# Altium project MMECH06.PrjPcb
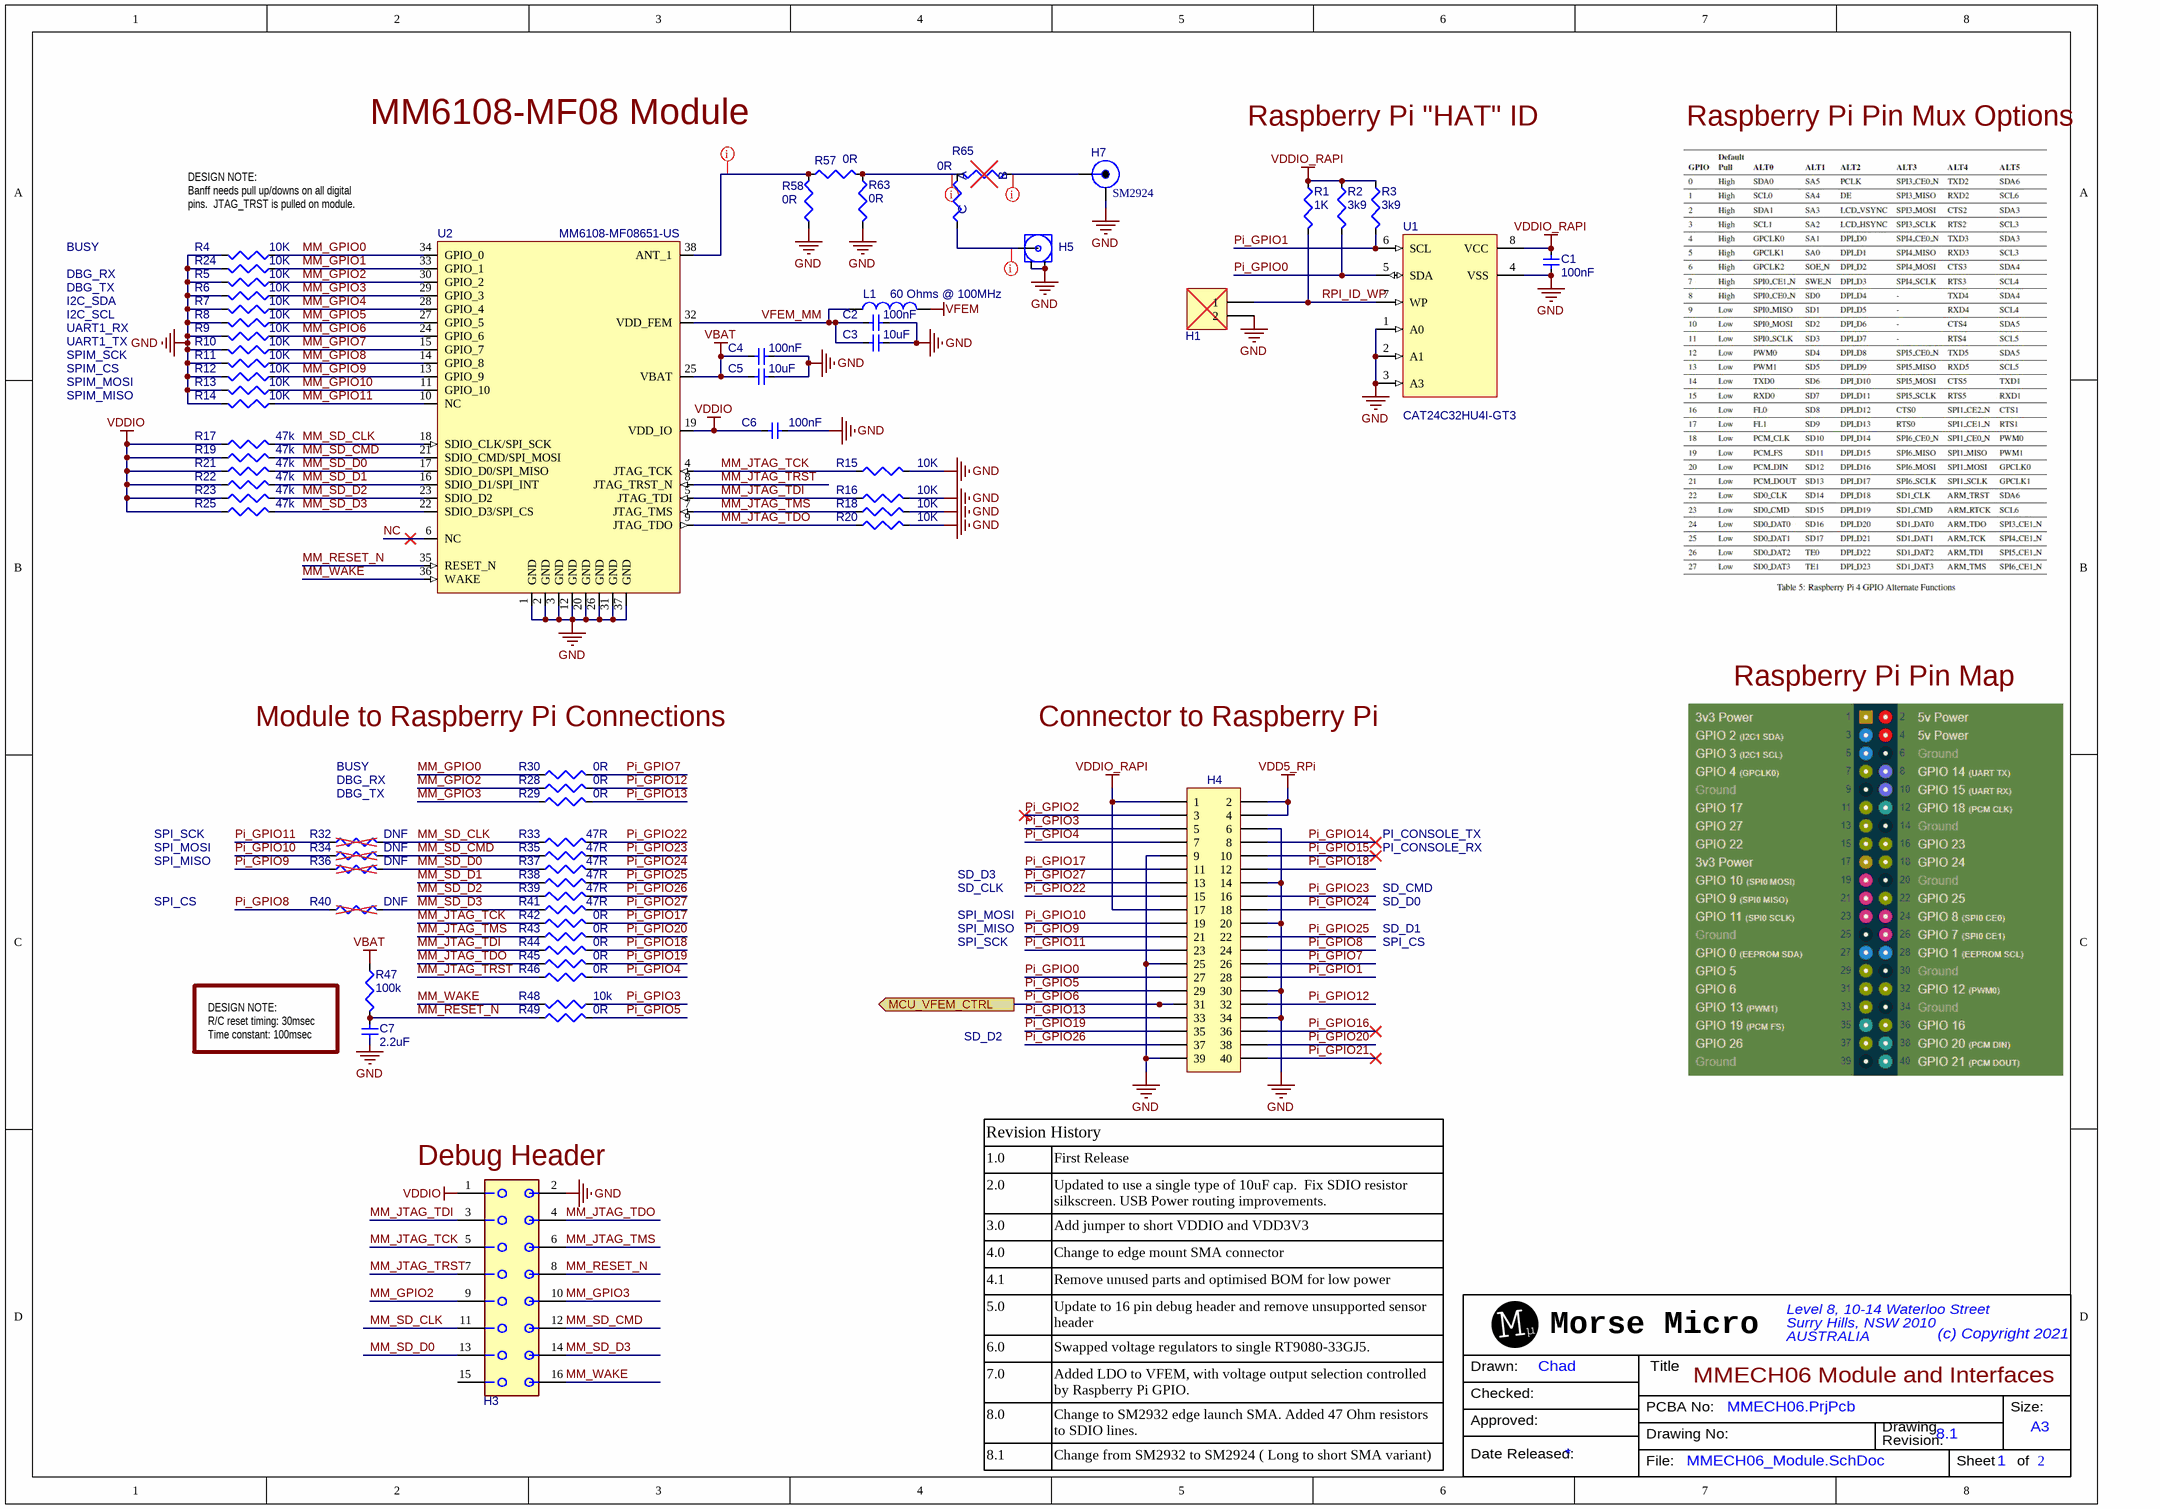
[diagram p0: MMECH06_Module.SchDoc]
Project: MM_EVC3; Revision: 1
2 sheets, 107 parts. Net scope: flat (ports and power ports of the same name join across sheets).
Board file: MMECH06.PcbDoc
Sheets:
  MMECH06_Module.SchDoc
  MMECH06_Power.SchDoc

## Sheet MMECH06_Module.SchDoc: MMECH06 Module and Interfaces
size A3; DrawnBy: Chad; Revision: 8.1; SheetNumber: 1; SheetTotal: 2; PageSetup: Record=PageOptions¦CenterHorizontal=True¦CenterVertical=True¦PrintScale=1.04¦XCorrection=1.00¦YCorrection=1.00¦PrintKind=0¦BorderSize=5000000¦LeftOffset=0¦BottomOffset=0¦Orientation=2¦PaperLength=1000¦PaperWidth=1000¦Scale=100¦PaperSource=7¦PrintQuality=-4¦MediaType=1¦DitherType=10¦PaperKind=A3¦PrintScaleMode=1

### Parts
C1  value 100nF  [CAPC1005X06N]  (hidden comment: CAP)
C2  value 100nF  [CAPC1005X06N]  (hidden comment: CAP)
C3  value 10uF  [CAPC1608X06N]  (hidden comment: CAP)
C4  value 100nF  [CAPC1005X06N]  (hidden comment: CAP)
C5  value 10uF  [CAPC1608X06N]  (hidden comment: CAP)
C6  value 100nF  [CAPC1005X06N]  (hidden comment: CAP)
C7  value 2.2uF  [CAPC1005X06N]  (hidden comment: CAP)
H1  HDR_1X2_DNF  [HDR1X2_DNF]  (value not drawn)  (no BOM)
H3  2X8_FTSH_DV_K  [FTSH_108_D_K]  (value not drawn)
H4  HDR_2X20  [HDR2X20F]  (value not drawn)
H5  U_FL-R-SMT  [U_FL-R-SMT]  (value not drawn)
H7  SM2924  [SM2924-Footprint-1]
L1  value 60 Ohms @ 100MHz  [INDC1005X06N]  (hidden comment: IND)
R1  value 1K  [RESC1005X04N]  (hidden comment: RES)
R2  value 3k9  [RESC1005X04N]  (hidden comment: RES)
R3  value 3k9  [RESC1005X04N]  (hidden comment: RES)
R4  value 10K  [RESC1005X04N]  (hidden comment: RES)
R5  value 10K  [RESC1005X04N]  (hidden comment: RES)
R6  value 10K  [RESC1005X04N]  (hidden comment: RES)
R7  value 10K  [RESC1005X04N]  (hidden comment: RES)
R8  value 10K  [RESC1005X04N]  (hidden comment: RES)
R9  value 10K  [RESC1005X04N]  (hidden comment: RES)
R10  value 10K  [RESC1005X04N]  (hidden comment: RES)
R11  value 10K  [RESC1005X04N]  (hidden comment: RES)
R12  value 10K  [RESC1005X04N]  (hidden comment: RES)
R13  value 10K  [RESC1005X04N]  (hidden comment: RES)
R14  value 10K  [RESC1005X04N]  (hidden comment: RES)
R15  value 10K  [RESC1005X04N]  (hidden comment: RES)
R16  value 10K  [RESC1005X04N]  (hidden comment: RES)
R17  value 47k  [RESC1005X04N]  (hidden comment: RES)
R18  value 10K  [RESC1005X04N]  (hidden comment: RES)
R19  value 47k  [RESC1005X04N]  (hidden comment: RES)
R20  value 10K  [RESC1005X04N]  (hidden comment: RES)
R21  value 47k  [RESC1005X04N]  (hidden comment: RES)
R22  value 47k  [RESC1005X04N]  (hidden comment: RES)
R23  value 47k  [RESC1005X04N]  (hidden comment: RES)
R24  value 10K  [RESC1005X04N]  (hidden comment: RES)
R25  value 47k  [RESC1005X04N]  (hidden comment: RES)
R28  value 0R  [RESC1608X06N]  (hidden comment: RES)
R29  value 0R  [RESC1608X06N]  (hidden comment: RES)
R30  value 0R  [RESC1608X06N]  (hidden comment: RES)
R32  value DNF  [RESC1608X06N_DNF]  (hidden comment: RES_DNF)  (no BOM)
R33  value 47R  [RESC1608X06N]  (hidden comment: RES)
R34  value DNF  [RESC1608X06N_DNF]  (hidden comment: RES_DNF)  (no BOM)
R35  value 47R  [RESC1608X06N]  (hidden comment: RES)
R36  value DNF  [RESC1608X06N_DNF]  (hidden comment: RES_DNF)  (no BOM)
R37  value 47R  [RESC1608X06N]  (hidden comment: RES)
R38  value 47R  [RESC1608X06N]  (hidden comment: RES)
R39  value 47R  [RESC1608X06N]  (hidden comment: RES)
R40  value DNF  [RESC1608X06N_DNF]  (hidden comment: RES_DNF)  (no BOM)
R41  value 47R  [RESC1608X06N]  (hidden comment: RES)
R42  value 0R  [RESC1608X06N]  (hidden comment: RES)
R43  value 0R  [RESC1608X06N]  (hidden comment: RES)
R44  value 0R  [RESC1608X06N]  (hidden comment: RES)
R45  value 0R  [RESC1608X06N]  (hidden comment: RES)
R46  value 0R  [RESC1608X06N]  (hidden comment: RES)
R47  value 100k  [0402_res_rnd]  (hidden comment: RES)
R48  value 10k  [RESC1608X06N]  (hidden comment: RES)
R49  value 0R  [RESC1608X06N]  (hidden comment: RES)
R57  value 0R  [RESC1608X06L]  (hidden comment: RES)
R58  value 0R  [RESC1608X06L]  (hidden comment: RES)
R63  value 0R  [RESC1608X06L]  (hidden comment: RES)
R65  value 0R  [0603_RES_AC_RA]  (hidden comment: RES_AC)
U1  CAT24C32HU4I-GT3  [DFN8]
U2  MM6108-MF08651-US  [MF04]

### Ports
MCU_VFEM_CTRL (out)

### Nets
GND: C1.2 C2.2 C3.2 C4.1 C5.2 C6.2 C7.2 H1.2 H3.2 H4.6 H4.9 H4.14 H4.20 H4.25 H4.30 H4.34 H4.39 H5.2 H5.3 H7.2 R4.2 R5.2 R6.2 R7.2 R8.2 R9.2 R10.2 R11.2 R12.2 R13.2 R14.2 R15.2 R16.2 R18.2 R20.2 R24.2 R58.1 R63.2 U1.1(A0) U1.2(A1) U1.3(A3) U1.4(VSS) U2.1(GND) U2.2(GND) U2.3(GND) U2.12(GND) U2.20(GND) U2.26(GND) U2.31(GND) U2.37(GND)
VBAT: C4.2 C5.1 R47.1 U2.25(VBAT)
VDD5_RPi: H4.2 H4.4
VDDIO: C6.1 H3.1 R17.1 R19.1 R21.2 R22.2 R23.2 R25.1 U2.19(VDD_IO)
VDDIO_RAPI: C1.1 H4.1 H4.17 R1.1 R2.1 R3.1 U1.8(VCC)
VFEM: L1.2
MM_GPIO0: R4.1 R30.1 U2.34(GPIO_0)
MM_GPIO1: R24.1 U2.33(GPIO_1)
MM_GPIO2: H3.9 R5.1 R28.1 U2.30(GPIO_2)
MM_GPIO3: H3.10 R6.1 R29.1 U2.29(GPIO_3)
MM_GPIO4: R7.1 U2.28(GPIO_4)
MM_GPIO5: R8.1 U2.27(GPIO_5)
MM_GPIO6: R9.1 U2.24(GPIO_6)
MM_GPIO7: R10.1 U2.15(GPIO_7)
MM_GPIO8: R11.1 U2.14(GPIO_8)
MM_GPIO9: R12.1 U2.13(GPIO_9)
MM_GPIO10: R13.1 U2.11(GPIO_10)
MM_GPIO11: R14.1 U2.10(NC)
MM_JTAG_TCK: H3.5 R15.1 R42.1 U2.4(JTAG_TCK)
MM_JTAG_TDI: H3.3 R16.1 R44.1 U2.5(JTAG_TDI)
MM_JTAG_TDO: H3.4 R20.1 R45.1 U2.9(JTAG_TDO)
MM_JTAG_TMS: H3.6 R18.1 R43.1 U2.7(JTAG_TMS)
MM_JTAG_TRST: H3.7 R46.1 U2.8(JTAG_TRST_N)
MM_RESET_N: C7.1 H3.8 R47.2 R49.1 U2.35(RESET_N)
MM_SD_CLK: H3.11 R17.2 R32.2 R33.1 U2.18(SDIO_CLK/SPI_SCK)
MM_SD_CMD: H3.12 R19.2 R34.2 R35.1 U2.21(SDIO_CMD/SPI_MOSI)
MM_SD_D0: H3.13 R21.1 R36.2 R37.1 U2.17(SDIO_D0/SPI_MISO)
MM_SD_D1: R22.1 R38.1 U2.16(SDIO_D1/SPI_INT)
MM_SD_D2: R23.1 R39.1 U2.23(SDIO_D2)
MM_SD_D3: H3.14 R25.2 R40.2 R41.1 U2.22(SDIO_D3/SPI_CS)
MM_WAKE: H3.16 R48.1 U2.36(WAKE)
NC: U2.6(NC)
Pi_GPIO0: H4.27 R2.2 U1.5(SDA)
Pi_GPIO1: H4.28 R3.2 U1.6(SCL)
Pi_GPIO2: H4.3
Pi_GPIO3: H4.5 R48.2
Pi_GPIO4: H4.7 R46.2
Pi_GPIO5: H4.29 R49.2
Pi_GPIO6: H4.31 ; port MCU_VFEM_CTRL
Pi_GPIO7: H4.26 R30.2
Pi_GPIO8: H4.24 R40.1
Pi_GPIO9: H4.21 R36.1
Pi_GPIO10: H4.19 R34.1
Pi_GPIO11: H4.23 R32.1
Pi_GPIO12: H4.32 R28.2
Pi_GPIO13: H4.33 R29.2
Pi_GPIO14: H4.8
Pi_GPIO15: H4.10
Pi_GPIO16: H4.36
Pi_GPIO17: H4.11 R42.2
Pi_GPIO18: H4.12 R44.2
Pi_GPIO19: H4.35 R45.2
Pi_GPIO20: H4.38 R43.2
Pi_GPIO21: H4.40
Pi_GPIO22: H4.15 R33.2
Pi_GPIO23: H4.16 R35.2
Pi_GPIO24: H4.18 R37.2
Pi_GPIO25: H4.22 R38.2
Pi_GPIO26: H4.37 R39.2
Pi_GPIO27: H4.13 R41.2
RPI_ID_WP: H1.1 R1.2 U1.7(WP)
VFEM_MM: C2.1 C3.1 L1.1 U2.32(VDD_FEM)
NetH5_1: H5.1 R65.C
NetH7_1: H7.1 R65.B
NetR57_1: R57.1 R58.2 U2.38(ANT_1)
NetR57_2: R57.2 R63.1 R65.A

Not connected (* = marked no-connect by the designer): H3 15

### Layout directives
net class RF-Net: NetH5_1, NetH7_1, NetR57_1, NetR57_2

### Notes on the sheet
- #800000
- MM6108-MF08 Module
- Raspberry Pi "HAT" ID
- Raspberry Pi Pin Mux Options
- DESIGN NOTE:
  Banff needs pull up/downs on all digital pins.  JTAG_TRST is pulled on module.
- DBG_RX
- DBG_TX
- BUSY
- I2C_SDA
- I2C_SCL
- SPIM_SCK
- SPIM_CS
- UART1_RX
- UART1_TX
- SPIM_MOSI
- SPIM_MISO
- Raspberry Pi Pin Map
- Module to Raspberry Pi Connections
- Connector to Raspberry Pi
- SPI_MOSI
- SPI_SCK
- PI_CONSOLE_TX
- PI_CONSOLE_RX
- SPI_MISO
- SPI_CS
- SD_CLK
- SD_D3
- SD_CMD
- SD_D0
- SD_D1
- DESIGN NOTE:
  R/C reset timing: 30msec
  Time constant: 100msec
- SD_D2
- (near H3) Debug Header
- Revision History
- 1.0
- First Release
- 2.0
- 3.0
- 4.0
- Updated to use a single type of 10uF cap.  Fix SDIO resistor silkscreen. USB Power routing improvements.
- Add jumper to short VDDIO and VDD3V3
- Change to edge mount SMA connector
- 4.1
- Remove unused parts and optimised BOM for low power
- 5.0
- 6.0
- 7.0
- Update to 16 pin debug header and remove unsupported sensor header
- Swapped voltage regulators to single RT9080-33GJ5.
- Added LDO to VFEM, with voltage output selection controlled by Raspberry Pi GPIO.
- 8.0
- Change to SM2932 edge launch SMA. Added 47 Ohm resistors to SDIO lines.
- 8.1
- Change from SM2932 to SM2924 ( Long to short SMA variant)

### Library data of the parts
C1 C2 C4 C6 = CAP0084: Cap,100nF,10V,+/-10%,X7R,0402; Manufacturer 1: Kemet; Manufacturer Part Number 1: C0402C104K8RACTU; Generic Allowed: Yes; Subtype: Ceramic; Tolerance: 10%
C3 C5 = CAP0164: CAP CER 10UF 25V 20% X5R 0603; Manufacturer 1: Murata, Inc.; Manufacturer Part Number 1: GRM188R61E106MA73J; Generic Allowed: Yes; Subtype: Ceramic
C7 = CAP0086: CAP CER 2.2UF 6.3V 20% X5R 0402; Manufacturer 1: Taiyo Yuden; Manufacturer Part Number 1: JMK105BJ225MV-F; Generic Allowed: Yes; Subtype: Ceramic
H1 = HDR0098: Conn Straight Header 2x1 0.100" 2 POS (DNF)
H3 = HDR0143: CONN,Vertical FTSH Series,0.05"16 Pins, Through Hole; Manufacturer 1: Samtec; Manufacturer Part Number 1: FTSH-108-01-F-D-K; Generic Allowed: No
H4 = HDR0151: Conn Female Header 20x2 0.100" 40 POS; Manufacturer 1: Sullins Electronics, Corp; Manufacturer Part Number 1: PPPC202LFBN-RC; Generic Allowed: Yes
H5 = CON0012: U.FL RF Connector; Manufacturer 1: Hirose; Manufacturer Part Number 1: U.FL-R-SMT; Generic Allowed: Yes
H7 = JCK0138-4: Wanshih RF SMD SMA connector with 2 GND pillars - Smaller Connector Barrel
L1 = IND0083: BEAD 60OHMS 2500MA 32 MOHM; Manufacturer 1: Murata; Manufacturer Part Number 1: BLM15PX600SN1D; Current: 2.5A; Generic Allowed: Yes; Resistance: 32mOhm
R1 = RES0004: RES SMD 1Kohm 1% 1/10W Thick film 0402; Manufacturer 1: Panasonic; Manufacturer Part Number 1: ERJ-2RKF1001X; Generic Allowed: Yes
R2 R3 = RES0204: RES SMD 3.9K OHM 1% 1/16W 0402; Manufacturer 1: Yageo; Manufacturer Part Number 1: RC0402FR-073K9L; Generic Allowed: Yes
R4-R16 R18 R20 R24 = RES0002: RES SMD 10Kohm 1% 1/10W Thick film 0402; Manufacturer 1: Panasonic; Manufacturer Part Number 1: ERJ-2RKF1002X; Generic Allowed: Yes
R17 R19 R21-R23 R25 = RES0086: Res, 47K Ohms,1/16W, 1%, 0402,SMD RoHS; Manufacturer 1: Rohm; Manufacturer Part Number 1: MCR01MZPF4702; Generic Allowed: Yes
R28-R30 R42-R46 R49 R57 R58 R63 = RES0119: Res, 0 Ohm, 1/10W,+/-5%,0603 RoHS; Manufacturer 1: Rohm; Manufacturer Part Number 1: MCR03EZPJ000; Generic Allowed: Yes; Tolerance: 5%
R32 R34 R36 R40 = RES0035: Update Later
R33 R35 R37-R39 R41 = RES0282: RES SMD 47 OHM 5% 1/10W 0603; Manufacturer 1: Panasonic Electronic Components; Manufacturer Part Number 1: ERJ-3GEYJ470V; Generic Allowed: Yes; Subtype: Thick Film
R47 = RES0044: Res,100K Ohms,1/16W, 1%, 0402,SMD RoHS; Manufacturer 1: Rohm; Manufacturer Part Number 1: MCR01MZPF1003; Generic Allowed: Yes
R48 = RES0124: Res, 10K Ohm, 1/10W,+/-1%,0603 RoHS; Manufacturer 1: Rohm; Manufacturer Part Number 1: MCR03EZPFX1002; Generic Allowed: Yes; Tolerance: 1%
R65 = RES0281: Ohms Jumper Chip Resistor 0603 ( 1608 Metric) - RES_AB; Manufacturer 1: Rohm; Manufacturer Part Number 1: MCR03EZPJ000; Generic Allowed: Yes; Power: 1/10W; Tolerance: 5%
U1 = ICT0220: IC EEPROM 32KBIT I2C 1MHZ 8UDFN; Manufacturer 1: OnSemi; Generic Allowed: No
U2 = MOD0018: MM61xx-MF08; Manufacturer Part Number 1: MM61xx-MF08251; Manufacturer 1: Morse Micro; Value: MM61xx-MF08251

## Sheet MMECH06_Power.SchDoc: MMECH06 Power & Reset
size A3; CompanyName: Morse Micro; DrawnBy: Chad; Revision: 8.1; SheetNumber: 2; SheetTotal: 2; pageName: Regulators; PageSetup: Record=PageOptions¦CenterHorizontal=True¦CenterVertical=True¦PrintScale=1.04¦XCorrection=1.00¦YCorrection=1.00¦PrintKind=0¦BorderSize=5000000¦LeftOffset=0¦BottomOffset=0¦Orientation=2¦PaperLength=1000¦PaperWidth=1000¦Scale=100¦PaperSource=7¦PrintQuality=-4¦MediaType=1¦DitherType=10¦PaperKind=A3¦PrintScaleMode=1
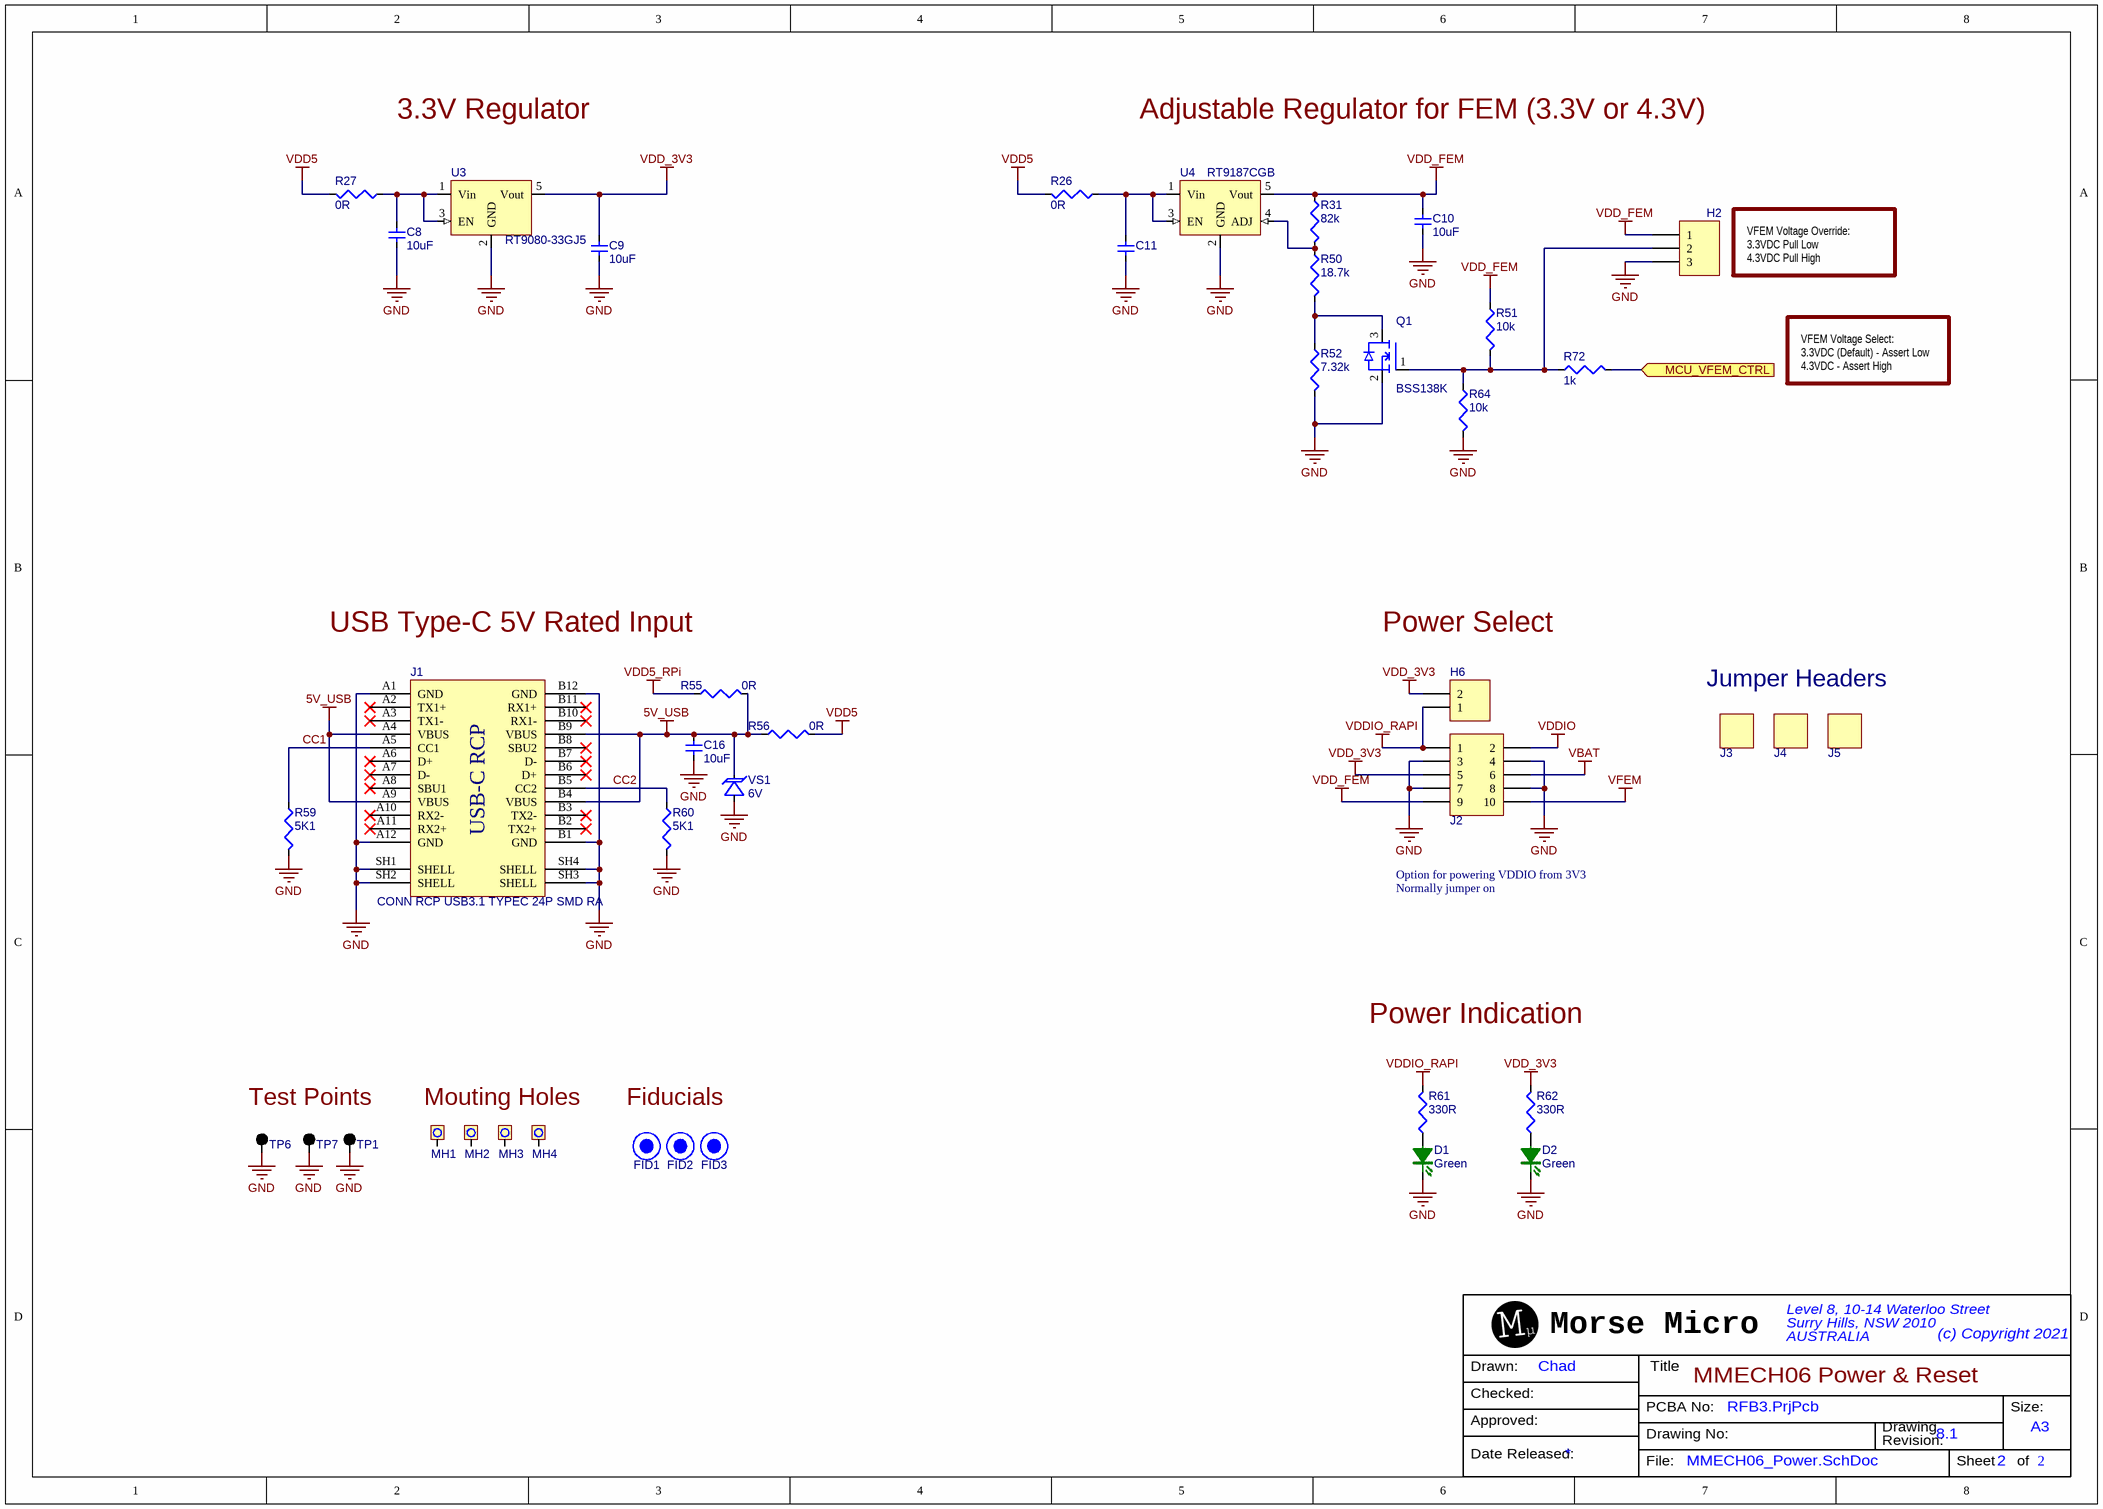
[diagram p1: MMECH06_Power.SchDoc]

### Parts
C8  value 10uF  [CAPC1608X06N]  (hidden comment: CAP)
C9  value 10uF  [CAPC1608X06N]  (hidden comment: CAP)
C10  value 10uF  [CAPC1608X06N]  (hidden comment: CAP)
C11  CAP  [CAPC1608X06N]  (value not drawn)
C16  value 10uF  [CAPC1608X06N]  (hidden comment: CAP)
D1  value Green  [LED_0402_GREEN]  (hidden comment: LED_G)
D2  value Green  [LED_0402_GREEN]  (hidden comment: LED_G)
FID1  FIDUCIAL  [FIDUCIAL_1MM]  (value not drawn)  (no BOM)
FID2  FIDUCIAL  [FIDUCIAL_1MM]  (value not drawn)  (no BOM)
FID3  FIDUCIAL  [FIDUCIAL_1MM]  (value not drawn)  (no BOM)
H2  HDR_1X3  [HPH1A03UA]  (value not drawn)
H6  HDR_1X2  [HDR1X2]  (value not drawn)
J1  CONN RCP USB3.1 TYPEC 24P SMD RA  [USB-C_RCP]
J2  HDR_2X5  [HDR2X5]  (value not drawn)
J3  QPC02SXGN-RC  [QPC02SXGN-RC]  (value not drawn)
J4  QPC02SXGN-RC  [QPC02SXGN-RC]  (value not drawn)
J5  QPC02SXGN-RC  [QPC02SXGN-RC]  (value not drawn)
MH1  MH_300_275_NPTH  [MH_300_275_NPTH]  (value not drawn)  (no BOM)
MH2  MH_300_275_NPTH  [MH_300_275_NPTH]  (value not drawn)  (no BOM)
MH3  MH_300_275_NPTH  [MH_300_275_NPTH]  (value not drawn)  (no BOM)
MH4  MH_300_275_NPTH  [MH_300_275_NPTH]  (value not drawn)  (no BOM)
Q1  value BSS138K  [SOT-23]  (hidden comment: MOSFET_NCH_LGD)
R26  value 0R  [RESC1608X06N]  (hidden comment: RES)
R27  value 0R  [RESC1608X06N]  (hidden comment: RES)
R31  value 82k  [0402_res_rnd]  (hidden comment: RES)
R50  value 18.7k  [0402_res_rnd]  (hidden comment: RES)
R51  value 10k  [RESC1005X04N]  (hidden comment: RES)
R52  value 7.32k  [0402_res_rnd]  (hidden comment: RES)
R55  value 0R  [RESC1608X06N]  (hidden comment: RES)
R56  value 0R  [RESC1608X06N]  (hidden comment: RES)
R59  value 5K1  [RESC1005X04N]  (hidden comment: RES)
R60  value 5K1  [RESC1005X04N]  (hidden comment: RES)
R61  value 330R  [RESC1005X04N]  (hidden comment: RES)
R62  value 330R  [RESC1005X04N]  (hidden comment: RES)
R64  value 10k  [RESC1005X04N]  (hidden comment: RES)
R72  value 1k  [0402_res_rnd]  (hidden comment: RES)
TP1  TP-BLK  [TP-100_BLACK]  (value not drawn)
TP6  TP-BLK  [TP-100_BLACK]  (value not drawn)
TP7  TP-BLK  [TP-100_BLACK]  (value not drawn)
U3  value RT9080-33GJ5  [SOT-23_5]  (hidden comment: LDO_REG2_EN)
U4  value RT9187CGB  [SOT-23_5]  (hidden comment: RT9187C)
VS1  value 6V  [DO-214AC]  (hidden comment: Varistor_Uni)

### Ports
MCU_VFEM_CTRL (in)

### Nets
5V_USB: C16.1 J1.A4(VBUS) J1.A9(VBUS) J1.B4(VBUS) J1.B9(VBUS) R55.2 R56.1 VS1.K
GND: C8.1 C9.1 C10.1 C11.1 C16.2 D1.K D2.K H2.3 J1.A1(GND) J1.A12(GND) J1.B1(GND) J1.B12(GND) J1.SH1(SHELL) J1.SH2(SHELL) J1.SH3(SHELL) J1.SH4(SHELL) J2.3 J2.4 J2.7 J2.8 Q1.2(S) R52.2 R59.2 R60.2 R64.2 TP1.1 TP6.1 TP7.1 U3.2(GND) U4.2(GND) VS1.A
VBAT: J2.6
VDD5: R26.2 R27.2 R56.2
VDD5_RPi: R55.1
VDD_3V3: C9.2 H6.2 J2.5 R62.2 U3.5(Vout)
VDD_FEM: C10.2 H2.1 J2.9 R31.1 R51.1 U4.5(Vout)
VDDIO: J2.2
VDDIO_RAPI: H6.1 J2.1 R61.2
VFEM: J2.10
CC1: J1.A5(CC1) R59.1
CC2: J1.B5(CC2) R60.1
Pi_GPIO6: R72.2 ; port MCU_VFEM_CTRL
NetC8_2: C8.2 R27.1 U3.1(Vin) U3.3(EN)
NetC11_2: C11.2 R26.1 U4.1(Vin) U4.3(EN)
NetD1_A: D1.A R61.1
NetD2_A: D2.A R62.1
NetH2_2: H2.2 Q1.1(G) R51.2 R64.1 R72.1
NetQ1_3: Q1.3(D) R50.2 R52.1
NetR31_2: R31.2 R50.1 U4.4(ADJ)

Not connected (* = marked no-connect by the designer): J1 A2(TX1+)* A3(TX1-)* A6(D+)* A7(D-)* A8(SBU1)* A10(RX2-)* A11(RX2+)* B2(TX2+)* B3(TX2-)* B6(D+)* B7(D-)* B8(SBU2)* B10(RX1-)* B11(RX1+)*; MH1 1; MH2 1; MH3 1; MH4 1

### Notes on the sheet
- 3.3V Regulator
- Adjustable Regulator for FEM (3.3V or 4.3V)
- VFEM Voltage Override:
  3.3VDC Pull Low
  4.3VDC Pull High
- VFEM Voltage Select:
  3.3VDC (Default) - Assert Low
  4.3VDC - Assert High
- USB Type-C 5V Rated Input
- Power Select
- Jumper Headers
- Option for powering VDDIO from 3V3
- Normally jumper on
- Power Indication
- Test Points
- Mouting Holes
- Fiducials

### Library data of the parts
C8-C11 C16 = CAP0164: as C3 on sheet MMECH06_Module
D1 D2 = DIO0046: LED GREEN 0402 SMD; Manufacturer 1: SunLED; Manufacturer Part Number 1: XZVGR68W-3; Generic Allowed: Yes; Voltage: 2.0V
FID1-FID3 = PAD0013: 1mm Round Fiducial, 0.5mm Space; Rule: UNIONINDEX{}0[]RULEKIND{}Clearance[]NETSCOPE{}AnyNet[]LAYERKIND{}SameLayer[]NAME{}Schematic Clearance Constraint[]GAP{}0mil[]UNIT{}Imperial[]PcbType{}ProtelPcb
H2 = HDR0169: CONN HEADER VERT 3POS 1.27MM; Manufacturer 1: Adam Tech; Manufacturer Part Number 1: HPH1-A-03-UA; Generic Allowed: Yes
H6 = HDR0006: Conn Straight Header 2x1 0.100" 2 POS; Manufacturer 1: Oupiin; Manufacturer Part Number 1: 2011-1X02G00SB-1; Generic Allowed: Yes
J1 = CON0045: Manufacturer 1: Molex; Generic Allowed: Yes
J2 = HDR0012: Conn Straight Header 5x2 0.100" 10 POS; Manufacturer 1: Molex/Waldom Electronics Corp; Manufacturer Part Number 1: 90131-0125; Generic Allowed: Yes
J3-J5 = HDR0170: CONN JUMPER SHORTING .100" GOLD; Manufacturer 1: Sullins Connector Solutions; Generic Allowed: Yes
MH1-MH4 = PAD0031: MH NPTH 3.00mm DIA 2.75mm HOLE
Q1 = TSR0024: MOSFET N-CH 50V 220MA SOT23-3; Manufacturer 1: onsemi; Generic Allowed: No
R26 R27 R55 R56 = RES0119: as R28 on sheet MMECH06_Module
R31 = RES0284: RES 82K OHM 1% 1/16W 0402; Manufacturer 1: Yageo; Manufacturer Part Number 1: RC0402FR-0782KL; Generic Allowed: Yes
R50 = RES0011: RES SMD 18.7K 1% 1/10W Thick film 0402; Manufacturer 1: Panasonic; Manufacturer Part Number 1: ERJ-2RKF1872X; Generic Allowed: Yes
R51 R64 = RES0244: RES SMD 10K OHM 0.1% 1/16W 0402; Manufacturer 1: YAGEO; Manufacturer Part Number 1: RT0402BRD0710KL; Generic Allowed: Yes; Subtype: Thick Film
R52 = RES0285: RES 7.32K OHM 1% 1/16W 0402; Manufacturer 1: Yageo; Manufacturer Part Number 1: RC0402FR-077K32L; Generic Allowed: Yes; Tolerance: 5%
R59 R60 = RES0094: Res, 5.1K Ohms, 1/16W, 1%, 0402,SMD; Manufacturer 1: Rohm; Manufacturer Part Number 1: MCR01MZPF5101; Generic Allowed: Yes
R61 R62 = RES0073: Res, 330 Ohms, 1/16W, 1%, 0402,SMD; Manufacturer 1: Rohm; Manufacturer Part Number 1: MCR01MZPF3300; Generic Allowed: Yes
R72 = RES0240: RES 1K OHM 0.5% 1/16W 0402; Manufacturer 1: YAGEO; Manufacturer Part Number 1: RC0402DR-071KL; Generic Allowed: Yes; Subtype: Thick Film
TP1 TP6 TP7 = CON0001: Test Point PCB, BLACK 0.040"D; Manufacturer 1: Keystone Electronics; Manufacturer Part Number 1: 5001; Generic Allowed: Yes
U3 = REG0071: IC REG LIN 3.3V 600MA TSOT23-5; Manufacturer 1: Richtek USA Inc.; Generic Allowed: No
U4 = REG0079: IC REG LDO ADJ 0.6A SOT23-5; Manufacturer 1: Richtek USA Inc.; Current: 600mA; Generic Allowed: No
VS1 = DIO0056: TVS DIODE 6V 10.3V DO214AC; Manufacturer 1: Littelfuse Inc.; Manufacturer Part Number 1: SMAJ6.0A; Current: 38.8A; Generic Allowed: Yes

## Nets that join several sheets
GND: MMECH06_Module (50 pins), MMECH06_Power (31 pins)
VBAT: MMECH06_Module (C4.2 C5.1 R47.1 U2.25), MMECH06_Power (J2.6)
VDD5_RPi: MMECH06_Module (H4.2 H4.4), MMECH06_Power (R55.1)
VDDIO: MMECH06_Module (9 pins), MMECH06_Power (J2.2)
VDDIO_RAPI: MMECH06_Module (7 pins), MMECH06_Power (H6.1 J2.1 R61.2)
VFEM: MMECH06_Module (L1.2), MMECH06_Power (J2.10)
Pi_GPIO6: MMECH06_Module (H4.31), MMECH06_Power (R72.2)

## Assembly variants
Full Variant: not fitted H1 R17 R32 R34 R36 R40 R51 R58 R63 U1
EKH Variant: not fitted H1 H2 H2 H3 H3 H7 H7 J1 R17 R32 R34 R36 R40 R51 R58 R63 TP1 TP6 TP7 U1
